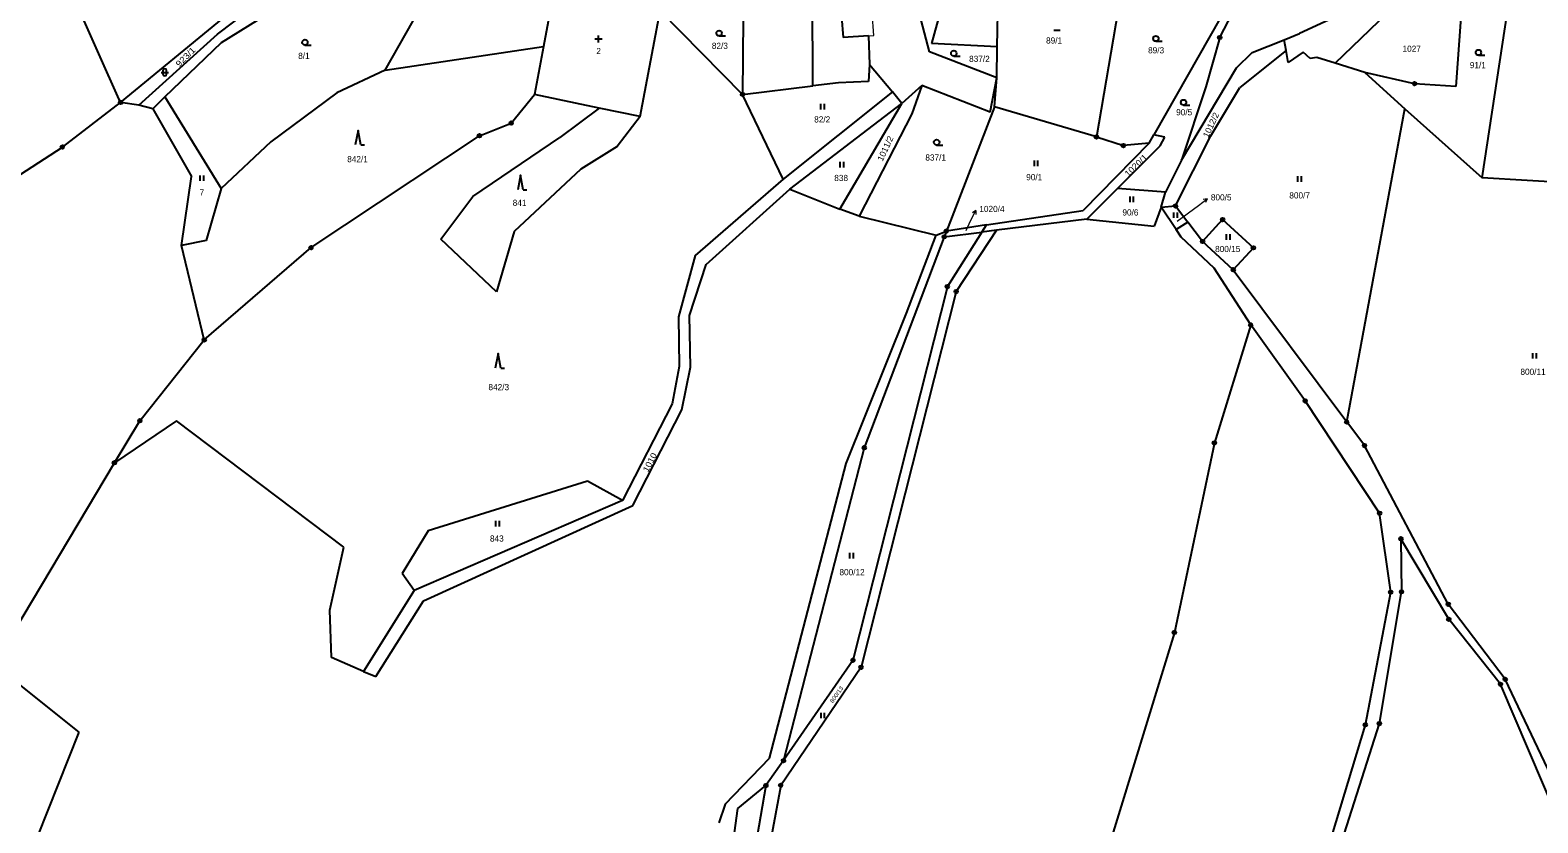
# Model space of a CAD drawing. Extents: x -754970 to -752637, y -970569 to -968179.
# Drawn here: x -753389.1 to -752973.4, y -969678.2 to -969459.8 of the extents above; entities that cross this region are included whole.
import ezdxf
from ezdxf.enums import TextEntityAlignment as Align

# ---------------------------------------------------------------- set-up
doc = ezdxf.new("R2010")
doc.units = 0
doc.header["$LTSCALE"] = 0.68
for name, color, linetype, lineweight in [('1', 7, 'Continuous', 25), ('3', 7, 'Continuous', 25), ('4', 7, 'Continuous', 13), ('7', 7, 'Continuous', 13), ('8', 7, 'Continuous', 25)]:
    doc.layers.add(name, color=color, linetype=linetype, lineweight=lineweight)
doc.layers.add('2', color=7, linetype='Continuous')

msp = doc.modelspace()

# ---------------------------------------------------------------- linework, layer by layer
at = {"layer": '1'}
for p, q in [((-753173.3, -969475.19), (-753173.46, -969436.06)), ((-753166.84, -969436.89), (-753164.98, -969461.87)), ((-753122.46, -969464.41), (-753122.01, -969438.33)), ((-753364.18, -969479.73), (-753379.75, -969444.91)), ((-753291.18, -969470.86), (-753276.41, -969444.75)), ((-753086.89, -969441.07), (-753095.11, -969489.22)), ((-753029.33, -969468.96), (-753004.33, -969444.88)), ((-753337.42, -969460.91), (-753320.74, -969448.28)), ((-753336.31, -969463.19), (-753312.73, -969448.51)), ((-753244.56, -969448.28), (-753247.56, -969464.32)), ((-753141.16, -969465.77), (-753145.99, -969447.24)), ((-753057.73, -969450.62), (-753079.26, -969488.65)), ((-753061.11, -969461.85), (-753055.32, -969450.6)), ((-752988.75, -969500.54), (-752980.96, -969449.2)), ((-753364.18, -969479.73), (-753335.83, -969456.43)), ((-753220.95, -969483.65), (-753215.39, -969454.46)), ((-753215.39, -969454.46), (-753192.67, -969477.51)), ((-753192.48, -969456.5), (-753192.67, -969477.51)), ((-753137.91, -969453.9), (-753140.6, -969463.48)), ((-753025.16, -969454.29), (-753039.13, -969460.76)), ((-752994.68, -969456.37), (-752996.05, -969475.33)), ((-753359.16, -969480.51), (-753337.42, -969460.91)), ((-753157.98, -969461.39), (-753164.98, -969461.87)), ((-753157.98, -969461.39), (-753157.64, -969469.25)), ((-753043.36, -969462.47), (-753039.13, -969460.76)), ((-753351.93, -969478.22), (-753336.31, -969463.19)), ((-753291.18, -969470.86), (-753247.56, -969464.32)), ((-753247.56, -969464.32), (-753250.03, -969477.53)), ((-753122.61, -969473), (-753141.16, -969465.77)), ((-753122.46, -969464.41), (-753140.6, -969463.48)), ((-753122.61, -969473), (-753122.46, -969464.41)), ((-753061.11, -969461.85), (-753064.96, -969475.48)), ((-753042.83, -969465.43), (-753055.54, -969475.64)), ((-753052.14, -969466.01), (-753043.36, -969462.47)), ((-753042.83, -969465.43), (-753043.36, -969462.47)), ((-753042.24, -969468.76), (-753042.83, -969465.43)), ((-753157.64, -969469.25), (-753157.92, -969473.93)), ((-753157.64, -969469.25), (-753151.36, -969476.85)), ((-753056.49, -969470.16), (-753052.14, -969466.01)), ((-753038.08, -969465.9), (-753042.24, -969468.76)), ((-753036.19, -969467.65), (-753038.08, -969465.9)), ((-753034.38, -969467.32), (-753036.19, -969467.65)), ((-753029.33, -969468.96), (-753034.38, -969467.32)), ((-753021.08, -969471.52), (-753029.33, -969468.96)), ((-753291.18, -969470.86), (-753304.52, -969477.08)), ((-753157.92, -969473.93), (-753166.19, -969474.3)), ((-753124.41, -969482.46), (-753122.61, -969473)), ((-753123.25, -969480.98), (-753122.61, -969473)), ((-753071.63, -969495.6), (-753056.49, -969470.16)), ((-753021.08, -969471.52), (-753010.12, -969481.47)), ((-753007.38, -969474.57), (-753021.08, -969471.52)), ((-753355.24, -969481.49), (-753351.93, -969478.22)), ((-753351.93, -969478.22), (-753336.41, -969503.47)), ((-753304.52, -969477.08), (-753322.79, -969490.63)), ((-753256.48, -969485.44), (-753250.03, -969477.53)), ((-753232.2, -969481.28), (-753250.03, -969477.53)), ((-753192.67, -969477.51), (-753173.3, -969475.19)), ((-753181.48, -969500.86), (-753192.67, -969477.51)), ((-753151.36, -969476.85), (-753181.48, -969500.86)), ((-753166.19, -969474.3), (-753173.3, -969475.19)), ((-753148.81, -969480), (-753151.36, -969476.85)), ((-753143.21, -969475.09), (-753148.81, -969480)), ((-753143.21, -969475.09), (-753146.05, -969482.85)), ((-753124.41, -969482.46), (-753143.21, -969475.09)), ((-753064.96, -969475.48), (-753071.63, -969495.6)), ((-753063.6, -969488.9), (-753055.54, -969475.64)), ((-752996.05, -969475.33), (-753007.38, -969474.57)), ((-753380.22, -969492.02), (-753364.18, -969479.73)), ((-753359.16, -969480.51), (-753364.18, -969479.73)), ((-753355.24, -969481.49), (-753359.16, -969480.51)), ((-753355.24, -969481.49), (-753344.59, -969500.15)), ((-753232.2, -969481.28), (-753243.03, -969489.4)), ((-753220.95, -969483.65), (-753232.2, -969481.28)), ((-753179.67, -969503.6), (-753148.81, -969480)), ((-753165.9, -969509.18), (-753148.81, -969480)), ((-753123.25, -969480.98), (-753136.49, -969515.16)), ((-753095.11, -969489.22), (-753123.25, -969480.98)), ((-753026.12, -969567.77), (-753010.12, -969481.47)), ((-753010.12, -969481.47), (-752988.75, -969500.54)), ((-753265.24, -969488.93), (-753256.48, -969485.44)), ((-753220.95, -969483.65), (-753227.22, -969491.89)), ((-753146.05, -969482.85), (-753160.55, -969511.11)), ((-753322.79, -969490.63), (-753336.41, -969503.47)), ((-753311.67, -969519.75), (-753265.24, -969488.93)), ((-753267.07, -969505.61), (-753243.03, -969489.4)), ((-753095.11, -969489.22), (-753087.66, -969491.62)), ((-753080.56, -969490.96), (-753079.26, -969488.65)), ((-753076.27, -969489.3), (-753079.26, -969488.65)), ((-753077.54, -969491.67), (-753076.27, -969489.3)), ((-753073.29, -969508.26), (-753063.6, -969488.9)), ((-753404.64, -969507.92), (-753380.22, -969492.02)), ((-753227.22, -969491.89), (-753237.27, -969498.11)), ((-753080.56, -969490.96), (-753098.75, -969509.5)), ((-753089.34, -969503.46), (-753077.54, -969491.67)), ((-753080.56, -969490.96), (-753087.66, -969491.62)), ((-753237.27, -969498.11), (-753255.62, -969515.32)), ((-753071.63, -969495.6), (-753076.1, -969504.46)), ((-753347.4, -969519.14), (-753344.59, -969500.15)), ((-752946.12, -969503.08), (-752988.75, -969500.54)), ((-753336.41, -969503.47), (-753340.62, -969517.81)), ((-753275.85, -969517.38), (-753267.07, -969505.61)), ((-753202.76, -969524.42), (-753179.67, -969503.6)), ((-753179.67, -969503.6), (-753165.9, -969509.18)), ((-753089.34, -969503.46), (-753097.79, -969511.91)), ((-753076.1, -969504.46), (-753089.34, -969503.46)), ((-753077.26, -969508.58), (-753076.1, -969504.46)), ((-753160.55, -969511.11), (-753165.9, -969509.18)), ((-753160.55, -969511.11), (-753139.27, -969516.29)), ((-753125.41, -969513.46), (-753098.75, -969509.5)), ((-753077.26, -969508.58), (-753079.24, -969513.8)), ((-753077.26, -969508.58), (-753073.29, -969508.26)), ((-753073.12, -969514.77), (-753077.26, -969508.58)), ((-753073.29, -969508.26), (-753069.94, -969512.68)), ((-753255.62, -969515.32), (-753260.56, -969531.91)), ((-753139.27, -969516.29), (-753136.49, -969515.16)), ((-753136.49, -969515.16), (-753137.1, -969516.77)), ((-753137.1, -969516.77), (-753126.69, -969515.47)), ((-753125.41, -969513.46), (-753136.49, -969515.16)), ((-753126.69, -969515.47), (-753136.22, -969530.48)), ((-753122.68, -969514.97), (-753133.79, -969531.84)), ((-753126.69, -969515.47), (-753125.41, -969513.46)), ((-753122.68, -969514.97), (-753126.69, -969515.47)), ((-753097.79, -969511.91), (-753122.68, -969514.97)), ((-753097.79, -969511.91), (-753079.24, -969513.8)), ((-753069.94, -969512.68), (-753073.12, -969514.77)), ((-753071.74, -969516.83), (-753073.12, -969514.77)), ((-753065.86, -969518.05), (-753069.94, -969512.68)), ((-753065.86, -969518.05), (-753060.32, -969512.01)), ((-753060.32, -969512.01), (-753051.82, -969519.8)), ((-753340.62, -969517.81), (-753347.4, -969519.14)), ((-753341.1, -969545.15), (-753347.4, -969519.14)), ((-753341.1, -969545.15), (-753311.67, -969519.75)), ((-753260.56, -969531.91), (-753275.85, -969517.38)), ((-753137.1, -969516.77), (-753159.11, -969574.88)), ((-753147.51, -969537.83), (-753139.27, -969516.29)), ((-753062.7, -969525.39), (-753071.74, -969516.83)), ((-753057.37, -969525.84), (-753065.86, -969518.05)), ((-753051.82, -969519.8), (-753057.37, -969525.84)), ((-753207.34, -969538.44), (-753202.76, -969524.42)), ((-753052.58, -969541.05), (-753062.7, -969525.39)), ((-753057.37, -969525.84), (-753026.12, -969567.77)), ((-753136.22, -969530.48), (-753162.24, -969633.45)), ((-753133.79, -969531.84), (-753160.02, -969635.34)), ((-753210.36, -969538.8), (-753210.19, -969552.52)), ((-753207.02, -969552.68), (-753207.34, -969538.44)), ((-753052.58, -969541.05), (-753062.59, -969573.53)), ((-753037.56, -969561.96), (-753052.58, -969541.05)), ((-753358.86, -969567.43), (-753341.1, -969545.15)), ((-753210.19, -969552.52), (-753212.07, -969562.75)), ((-753209.43, -969564.41), (-753207.02, -969552.68)), ((-753212.07, -969562.75), (-753225.83, -969589.41)), ((-753222.9, -969590.78), (-753209.43, -969564.41)), ((-753017.05, -969592.91), (-753037.56, -969561.96)), ((-753348.71, -969567.42), (-753365.88, -969579.01)), ((-753365.88, -969579.01), (-753358.86, -969567.43)), ((-753302.66, -969602.31), (-753348.71, -969567.42)), ((-753021.21, -969574.26), (-753026.12, -969567.77)), ((-753062.59, -969573.53), (-753073.6, -969625.75)), ((-753159.11, -969574.88), (-753181.39, -969661.08)), ((-752998.11, -969617.99), (-753021.21, -969574.26)), ((-753399.04, -969634.59), (-753365.88, -969579.01)), ((-753235.42, -969584.06), (-753279.34, -969597.81)), ((-753225.83, -969589.41), (-753235.42, -969584.06)), ((-753225.83, -969589.41), (-753283.24, -969614.22)), ((-753280.61, -969617.05), (-753222.9, -969590.78)), ((-753013.98, -969614.66), (-753017.05, -969592.91)), ((-753279.34, -969597.81), (-753286.56, -969609.53)), ((-753306.47, -969619.6), (-753302.66, -969602.31)), ((-753011.18, -969599.96), (-753011, -969614.57)), ((-752997.97, -969622.14), (-753011.18, -969599.96)), ((-753283.24, -969614.22), (-753286.56, -969609.53)), ((-753283.24, -969614.22), (-753297.21, -969636.49)), ((-753020.97, -969651.19), (-753013.98, -969614.66)), ((-753017.09, -969650.86), (-753011, -969614.57)), ((-753305.98, -969632.69), (-753306.47, -969619.6)), ((-753293.79, -969637.86), (-753280.61, -969617.05)), ((-752982.41, -969638.67), (-752998.11, -969617.99)), ((-752983.71, -969640.05), (-752997.97, -969622.14)), ((-753073.6, -969625.75), (-753104.65, -969726.56)), ((-753375.58, -969653.2), (-753399.04, -969634.59)), ((-753297.21, -969636.49), (-753305.98, -969632.69)), ((-753160.02, -969635.34), (-753182.17, -969667.89)), ((-753162.24, -969633.45), (-753181.39, -969661.08)), ((-753297.21, -969636.49), (-753293.79, -969637.86)), ((-752968.11, -969676.59), (-752983.71, -969640.05)), ((-752967.07, -969670.91), (-752982.41, -969638.67)), ((-753031.42, -969685.83), (-753020.97, -969651.19)), ((-753029.13, -969688.59), (-753017.09, -969650.86)), ((-753386.98, -969681.93), (-753375.58, -969653.2)), ((-753197.52, -969673.05), (-753185.25, -969660.38)), ((-753181.39, -969661.08), (-753186.24, -969667.95)), ((-753186.24, -969667.95), (-753195.3, -969720.48)), ((-753193.96, -969674.27), (-753186.24, -969667.95)), ((-753182.17, -969667.89), (-753191.87, -969721.17)), ((-753197.52, -969673.05), (-753199.21, -969678.21)), ((-753198.27, -969705.31), (-753193.96, -969674.27))]:
    msp.add_line(p, q, dxfattribs=at)
for points in [[(-753181.48, -969500.86), (-753205.74, -969521.92), (-753210.36, -969538.8)], [(-753185.25, -969660.38), (-753164.08, -969579.19), (-753147.51, -969537.83)]]:
    msp.add_lwpolyline(points, dxfattribs=at)
at = {"layer": '3'}
for p, q in [((-753232.39, -969463.27), (-753232.39, -969461.27)), ((-753199.153, -969461.43), (-753197.403, -969461.43)), ((-753106.863, -969459.83), (-753105.113, -969459.83)), ((-753313.343, -969463.93), (-753311.593, -969463.93)), ((-753231.389, -969462.271), (-753233.391, -969462.271)), ((-753078.713, -969462.88), (-753076.963, -969462.88)), ((-753134.453, -969466.96), (-753132.703, -969466.96)), ((-752989.783, -969466.73), (-752988.033, -969466.73)), ((-753352.981, -969471.451), (-753350.979, -969471.451)), ((-753352.481, -969470.951), (-753352.481, -969471.952)), ((-753351.479, -969471.952), (-753351.479, -969470.951)), ((-753171.091, -969481.65), (-753171.091, -969480.15)), ((-753170.09, -969481.65), (-753170.09, -969480.15)), ((-753071.093, -969480.49), (-753069.343, -969480.49)), ((-753297.95, -969491.43), (-753296.954, -969491.43)), ((-753139.173, -969491.48), (-753137.423, -969491.48)), ((-753165.741, -969497.62), (-753165.741, -969496.12)), ((-753164.74, -969497.62), (-753164.74, -969496.12)), ((-753112.231, -969497.27), (-753112.231, -969495.77)), ((-753111.23, -969497.27), (-753111.23, -969495.77)), ((-753342.201, -969501.37), (-753342.201, -969499.87)), ((-753341.2, -969501.37), (-753341.2, -969499.87)), ((-753039.601, -969501.59), (-753039.601, -969500.09)), ((-753038.6, -969501.59), (-753038.6, -969500.09)), ((-753253.15, -969503.81), (-753252.154, -969503.81)), ((-753085.851, -969507.19), (-753085.851, -969505.69)), ((-753084.85, -969507.19), (-753084.85, -969505.69)), ((-753073.801, -969511.54), (-753073.801, -969510.04)), ((-753072.8, -969511.54), (-753072.8, -969510.04)), ((-753059.241, -969517.57), (-753059.241, -969516.07)), ((-753058.24, -969517.57), (-753058.24, -969516.07)), ((-752974.821, -969550.3), (-752974.821, -969548.8)), ((-752973.82, -969550.3), (-752973.82, -969548.8)), ((-753259.35, -969552.94), (-753258.354, -969552.94)), ((-753260.691, -969596.53), (-753260.691, -969595.03)), ((-753259.69, -969596.53), (-753259.69, -969595.03)), ((-753163.081, -969605.37), (-753163.081, -969603.87)), ((-753162.08, -969605.37), (-753162.08, -969603.87)), ((-753171.051, -969649.4), (-753171.051, -969647.9)), ((-753170.05, -969649.4), (-753170.05, -969647.9))]:
    msp.add_line(p, q, dxfattribs=at)
for points in [[(-753297.95, -969491.43), (-753298.7, -969487.43), (-753299.45, -969491.43)], [(-753253.15, -969503.81), (-753253.9, -969499.81), (-753254.65, -969503.81)], [(-753259.35, -969552.94), (-753260.1, -969548.94), (-753260.85, -969552.94)]]:
    msp.add_lwpolyline(points, dxfattribs=at)
for centre in [(-753199.1529, -969460.6798), (-753078.7129, -969462.1298), (-753313.3429, -969463.1798), (-753134.4529, -969466.2098), (-752989.7829, -969465.9798), (-753071.0929, -969479.7398), (-753139.1729, -969490.7298)]:
    msp.add_circle(centre, 0.75, dxfattribs=at)
for centre, start, end in [((-753351.98, -969470.9509), 0, 180), ((-753351.98, -969471.9509), 180, 359.98789)]:
    msp.add_arc(centre, 0.5, start, end, dxfattribs=at)
at = {"layer": '4'}
msp.add_lwpolyline([(-753157.98, -969461.39), (-753156.5, -969461.29), (-753158.32, -969436.22)], dxfattribs=at)
at = {"layer": '7'}
for p, q in [((-753064.573, -969506.294), (-753065.674, -969506.497)), ((-753128.384, -969509.513), (-753129.274, -969510.193))]:
    msp.add_line(p, q, dxfattribs=at)
for points in [[(-753072.83, -969512.47), (-753066.97, -969508.1), (-753064.573, -969506.294), (-753065.072, -969507.297)], [(-753131.03, -969514.98), (-753129.7, -969512.21), (-753128.384, -969509.513), (-753128.373, -969510.632)]]:
    msp.add_lwpolyline(points, dxfattribs=at)
at = {"layer": '8'}
for centre, radius in [((-753061.11, -969461.8499), 0.5), ((-753061.11, -969461.8499), 0.0303), ((-753007.38, -969474.5699), 0.5), ((-753192.67, -969477.5099), 0.5), ((-753192.67, -969477.5099), 0.0303), ((-753007.38, -969474.5699), 0.0303), ((-753364.18, -969479.7299), 0.5), ((-753364.18, -969479.7299), 0.0303), ((-753256.48, -969485.4399), 0.5), ((-753256.48, -969485.4399), 0.0303), ((-753265.24, -969488.9299), 0.5), ((-753265.24, -969488.9299), 0.0303), ((-753095.11, -969489.2199), 0.5), ((-753095.11, -969489.2199), 0.0303), ((-753380.22, -969492.0199), 0.5), ((-753380.22, -969492.0199), 0.0303), ((-753087.66, -969491.6199), 0.5), ((-753087.66, -969491.6199), 0.0303), ((-753073.29, -969508.2599), 0.5), ((-753073.29, -969508.2599), 0.0303), ((-753060.32, -969512.0099), 0.5), ((-753136.49, -969515.1599), 0.5), ((-753136.49, -969515.1599), 0.0303), ((-753060.32, -969512.0099), 0.0303), ((-753311.67, -969519.7499), 0.5), ((-753311.67, -969519.7499), 0.0303), ((-753137.1, -969516.7699), 0.5), ((-753137.1, -969516.7699), 0.0303), ((-753065.86, -969518.0499), 0.5), ((-753065.86, -969518.0499), 0.0303), ((-753051.82, -969519.7999), 0.5), ((-753051.82, -969519.7999), 0.0303), ((-753057.37, -969525.8399), 0.5), ((-753057.37, -969525.8399), 0.0303), ((-753136.22, -969530.4799), 0.5), ((-753136.22, -969530.4799), 0.0303), ((-753133.79, -969531.8399), 0.5), ((-753133.79, -969531.8399), 0.0303), ((-753052.58, -969541.0499), 0.5), ((-753341.1, -969545.1499), 0.5), ((-753052.58, -969541.0499), 0.0303), ((-753341.1, -969545.1499), 0.0303), ((-753037.56, -969561.9599), 0.5), ((-753037.56, -969561.9599), 0.0303), ((-753358.86, -969567.4299), 0.5), ((-753358.86, -969567.4299), 0.0303), ((-753026.12, -969567.7699), 0.5), ((-753026.12, -969567.7699), 0.0303), ((-753062.59, -969573.5299), 0.5), ((-753062.59, -969573.5299), 0.0303), ((-753021.21, -969574.2599), 0.5), ((-753159.11, -969574.8799), 0.5), ((-753159.11, -969574.8799), 0.0303), ((-753021.21, -969574.2599), 0.0303), ((-753365.88, -969579.0099), 0.5), ((-753365.88, -969579.0099), 0.0303), ((-753017.05, -969592.9099), 0.5), ((-753017.05, -969592.9099), 0.0303), ((-753011.18, -969599.9599), 0.5), ((-753011.18, -969599.9599), 0.0303), ((-753013.98, -969614.6599), 0.5), ((-753013.98, -969614.6599), 0.0303), ((-753011, -969614.5699), 0.5), ((-753011, -969614.5699), 0.0303), ((-752998.11, -969617.9899), 0.5), ((-752998.11, -969617.9899), 0.0303), ((-752997.97, -969622.1399), 0.5), ((-752997.97, -969622.1399), 0.0303), ((-753073.6, -969625.7499), 0.5), ((-753073.6, -969625.7499), 0.0303), ((-753162.24, -969633.4499), 0.5), ((-753162.24, -969633.4499), 0.0303), ((-753160.02, -969635.3399), 0.5), ((-753160.02, -969635.3399), 0.0303), ((-752983.71, -969640.0499), 0.5), ((-752983.71, -969640.0499), 0.0303), ((-752982.41, -969638.6699), 0.5), ((-752982.41, -969638.6699), 0.0303), ((-753020.97, -969651.1899), 0.5), ((-753020.97, -969651.1899), 0.0303), ((-753017.09, -969650.8599), 0.5), ((-753017.09, -969650.8599), 0.0303), ((-753181.39, -969661.0799), 0.5), ((-753181.39, -969661.0799), 0.0303), ((-753186.24, -969667.9499), 0.5), ((-753186.24, -969667.9499), 0.0303), ((-753182.17, -969667.8899), 0.5), ((-753182.17, -969667.8899), 0.0303)]:
    msp.add_circle(centre, radius, dxfattribs=at)

# ---------------------------------------------------------------- texts
at = {"layer": '2'}
for s, height, rotation, width, p in [('923/1', 1.7, 45, 1.15, (-753345.6625, -969467.8035)), ('1012/2', 1.7, 65, 1.05, (-753062.7489, -969486.2967)), ('1011/2', 1.7, 65, 1.05, (-753152.5389, -969492.7967)), ('1020/1', 1.7, 44, 1.1, (-753083.624, -969497.6948)), ('1010', 1.7, 62, 1.1, (-753217.4762, -969579.2956)), ('800/13', 1.14, 55, 1.1, (-753166.2992, -969643.1964))]:
    msp.add_text(s, height=height, rotation=rotation, dxfattribs=dict(at, width=width)).set_placement(p, align=Align.CENTER)
for s, p in [('2', (-753232.37, -969466.415)), ('82/3', (-753198.939, -969464.985)), ('89/1', (-753106.789, -969463.515)), ('89/3', (-753078.659, -969466.215)), ('1027', (-753008.19, -969465.795)), ('8/1', (-753313.62, -969467.745)), ('837/2', (-753127.38, -969468.585)), ('91/1', (-752989.949, -969470.305)), ('90/5', (-753070.929, -969483.285)), ('82/2', (-753170.719, -969485.265)), ('842/1', (-753298.84, -969496.205)), ('837/1', (-753139.44, -969495.755)), ('838', (-753165.499, -969501.395)), ('90/1', (-753112.279, -969501.175)), ('7', (-753341.74, -969505.335)), ('841', (-753254.159, -969508.235)), ('800/7', (-753039.09, -969506.195)), ('90/6', (-753085.739, -969510.895)), ('800/15', (-753058.92, -969520.965)), ('800/11', (-752974.73, -969554.795)), ('842/3', (-753259.9, -969559.015)), ('843', (-753260.429, -969600.725)), ('800/12', (-753162.49, -969610.005))]:
    msp.add_text(s, height=1.7, dxfattribs=at).set_placement(p, align=Align.CENTER)
for s, p in [('800/5', (-753063.56, -969506.735)), ('1020/4', (-753127.4, -969509.935))]:
    msp.add_text(s, height=1.7, dxfattribs=at).set_placement(p)

doc.saveas('drawing.dxf')
